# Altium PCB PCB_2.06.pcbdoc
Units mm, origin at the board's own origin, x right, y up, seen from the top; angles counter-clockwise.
Board outline 118.7 x 80.7 mm, 2 copper layers (Top Layer, Bottom Layer); 48 components, 30 nets, 171 pads, 58 vias.
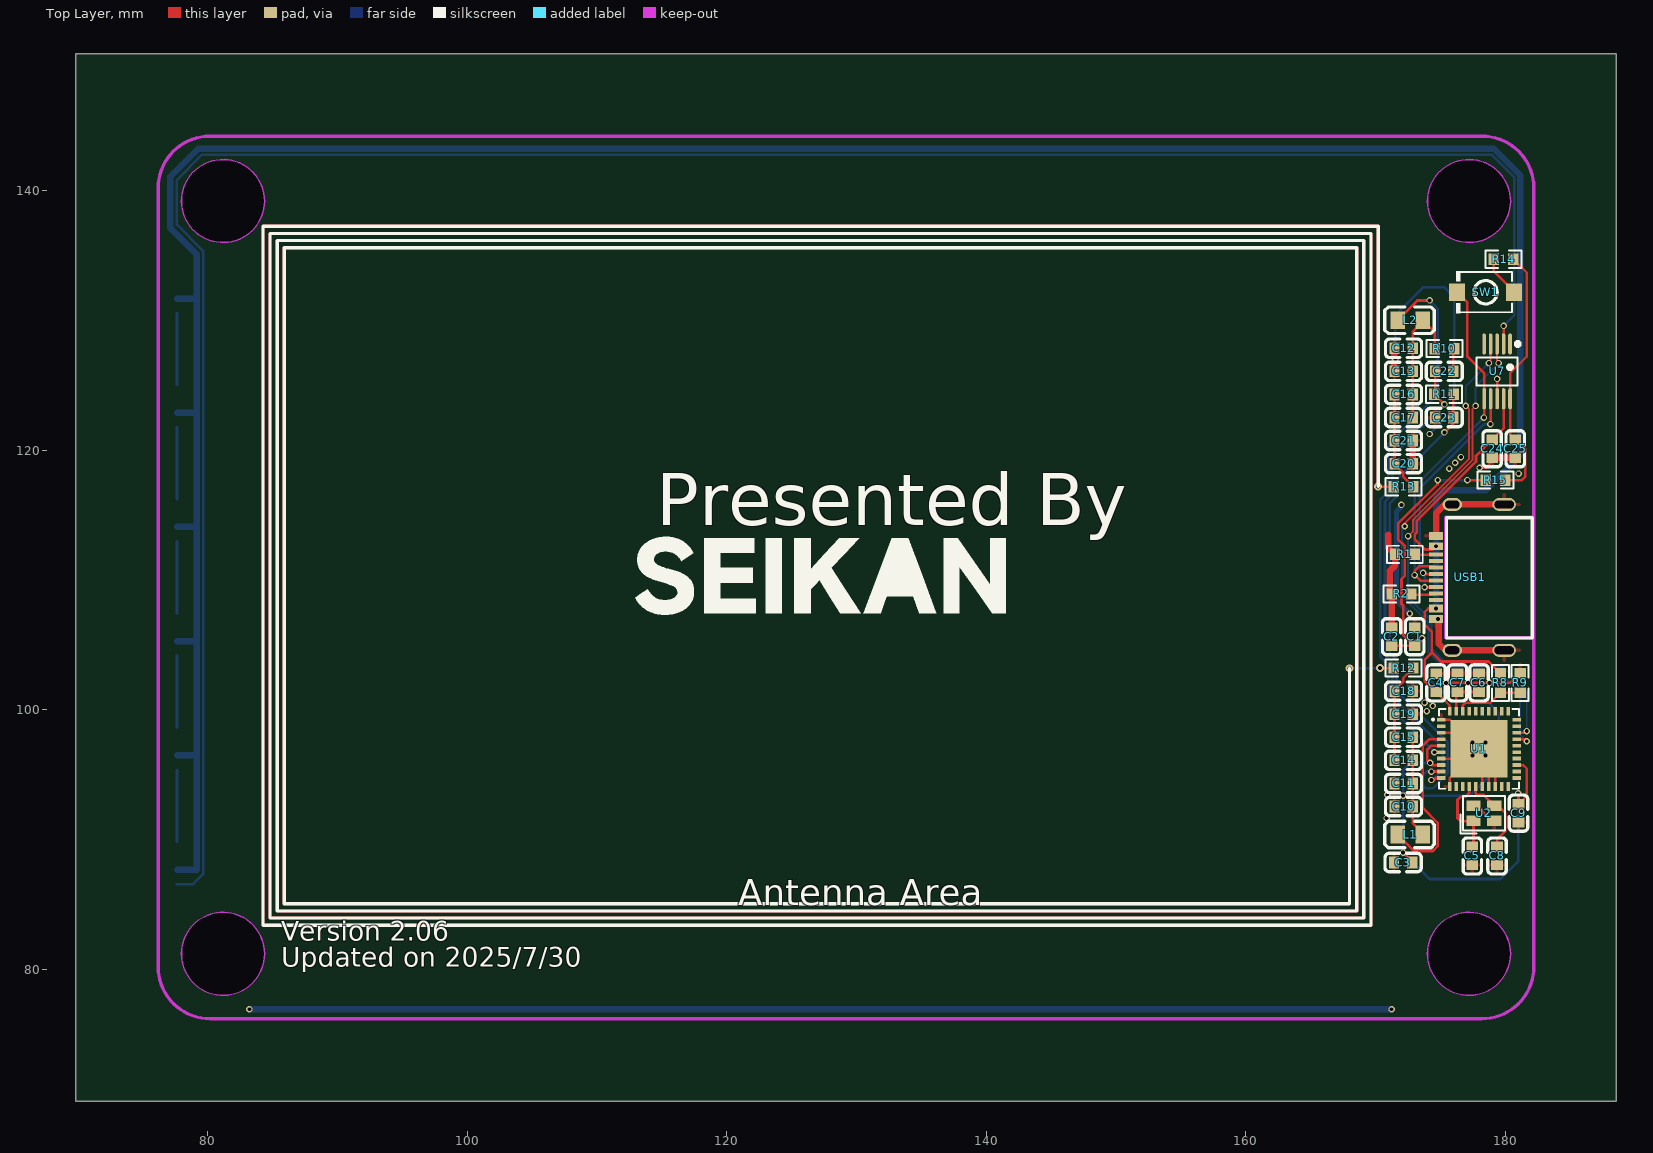
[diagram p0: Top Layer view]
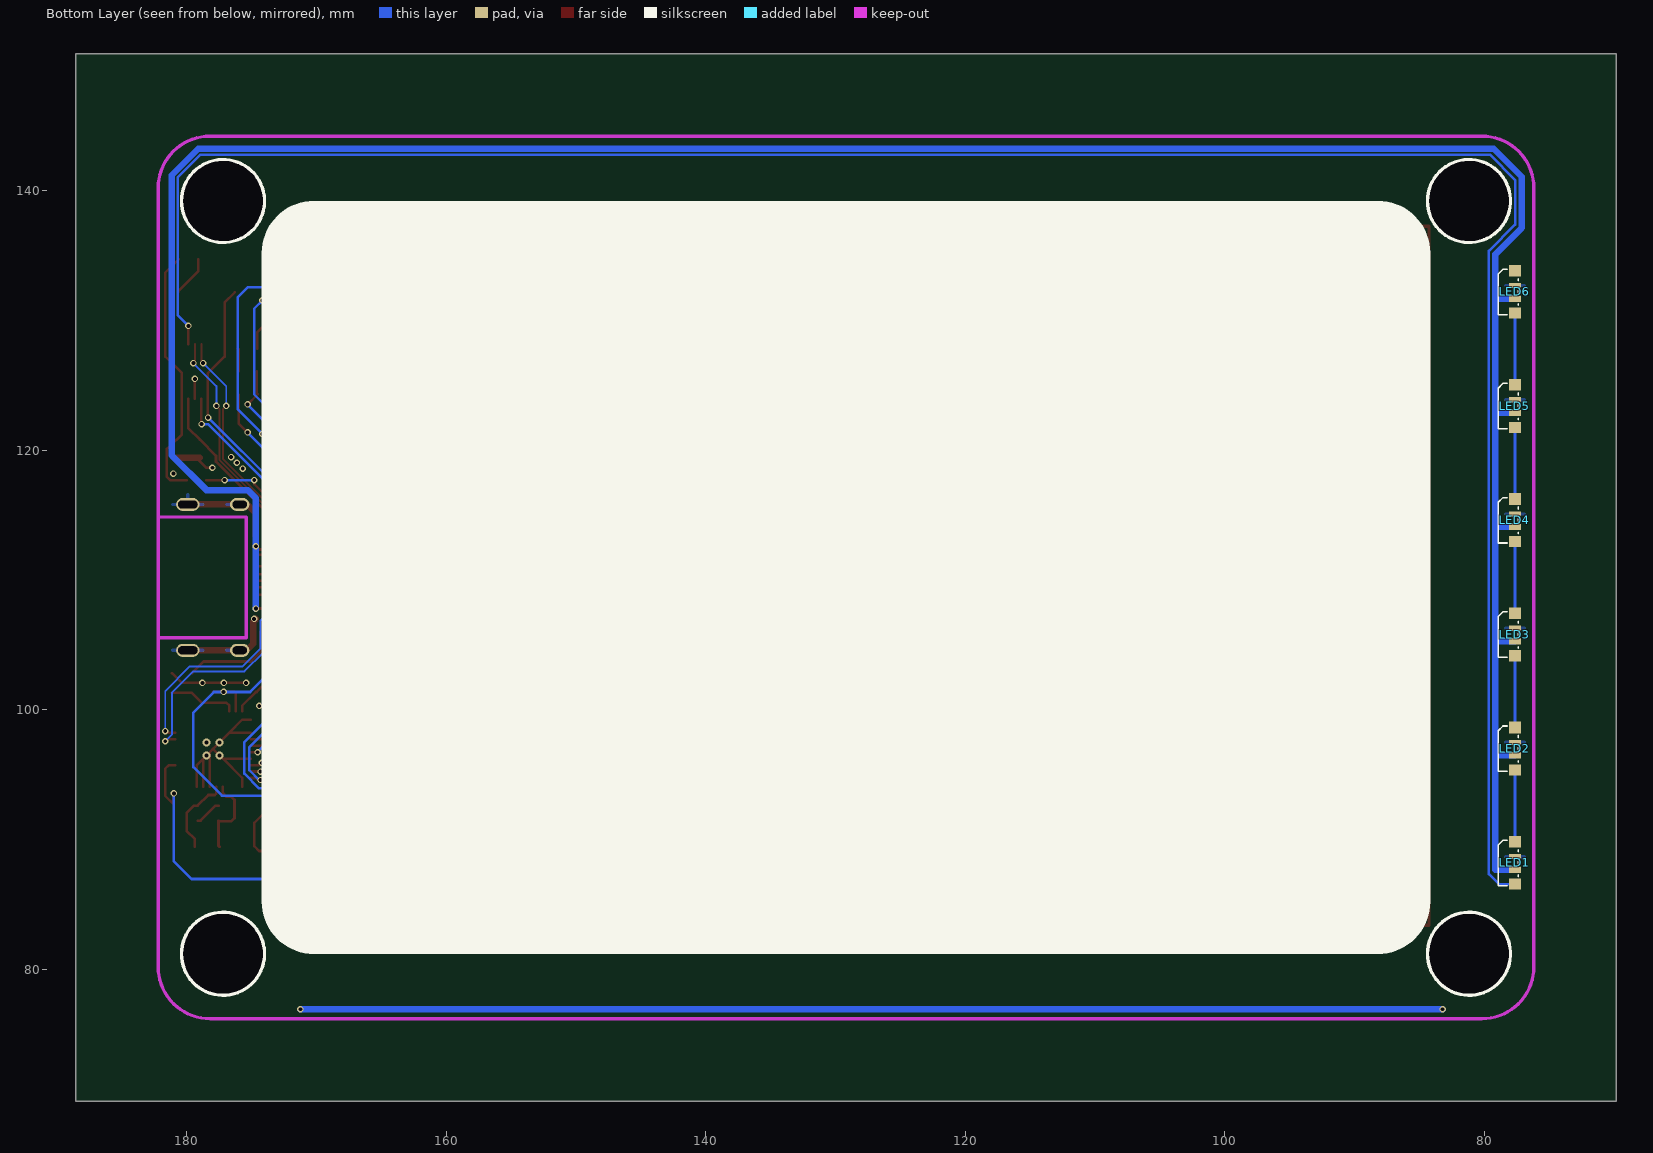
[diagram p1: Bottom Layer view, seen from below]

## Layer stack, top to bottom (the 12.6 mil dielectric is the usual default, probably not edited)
Top Layer: signal copper (thickness not stored)
Dielectric: dielectric 0.32, FR-4, Dk 4.8
Bottom Layer: signal copper (thickness not stored)

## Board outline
188.55,69.85 69.85,69.85 69.85,150.55 188.55,150.55
cut-out: 180.4,81.2 cw(c177.2,81.2) 174,81.2 cw(c177.2,81.2)
cut-out: 180.4,139.2 cw(c177.2,139.2) 174,139.2 cw(c177.2,139.2)
cut-out: 84.4,81.2 cw(c81.2,81.2) 78,81.2 cw(c81.2,81.2)
cut-out: 84.4,139.2 cw(c81.2,139.2) 78,139.2 cw(c81.2,139.2)

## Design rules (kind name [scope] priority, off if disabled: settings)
BoardOutlineClearance copperThickness1oz [All] p0: genericclearance=0.254 ignorepadtopadclearanceinfootprint=FALSE except(0: SMDPad-OutlineEdge Track-CutoutEdge SMDPad-CutoutEdge Arc-SplitContinuation Track-SplitContinuation SMDPad-SplitContinuation THPad-SplitContinuation Via-SplitContinuation Fill-SplitContinuation Poly-SplitContinuation Region-SplitContinuation Text-SplitContinuation; 0.152: THPad-CutoutEdge Via-CutoutEdge Fill-CutoutEdge Region-CutoutEdge; 0.3: Track-OutlineEdge THPad-OutlineEdge Via-OutlineEdge Fill-OutlineEdge Region-OutlineEdge Poly-OutlineEdge Text-OutlineEdge)
BoardOutlineClearance copperThickness2oz [All] p0: genericclearance=0.254 ignorepadtopadclearanceinfootprint=FALSE except(0: Arc-SplitContinuation Track-SplitContinuation SMDPad-SplitContinuation THPad-SplitContinuation Via-SplitContinuation Fill-SplitContinuation Poly-SplitContinuation Region-SplitContinuation Text-SplitContinuation; 0.152: SMDPad-CutoutEdge THPad-CutoutEdge Via-CutoutEdge Fill-CutoutEdge Region-CutoutEdge; 0.3: Track-OutlineEdge SMDPad-OutlineEdge THPad-OutlineEdge Via-OutlineEdge Fill-OutlineEdge Region-OutlineEdge Poly-OutlineEdge Text-OutlineEdge Track-CutoutEdge)
BoardOutlineClearance antenna [All] p0: genericclearance=0.254 ignorepadtopadclearanceinfootprint=FALSE except(0: Arc-SplitContinuation Track-SplitContinuation SMDPad-SplitContinuation THPad-SplitContinuation Via-SplitContinuation Fill-SplitContinuation Poly-SplitContinuation Region-SplitContinuation Text-SplitContinuation; 0.152: Track-CutoutEdge SMDPad-CutoutEdge THPad-CutoutEdge Via-CutoutEdge Fill-CutoutEdge Region-CutoutEdge; 0.3: Track-OutlineEdge SMDPad-OutlineEdge THPad-OutlineEdge Via-OutlineEdge Fill-OutlineEdge Region-OutlineEdge Poly-OutlineEdge Text-OutlineEdge)
Clearance copperThickness1oz [(InNet('TX1') OR InNet('TX2') OR InNet('GND') OR InNet('+3V3') OR InNet('VMID') OR InNet('RX') OR InNet('+5V') OR InNet('$1N4488') OR InNet('$1N4481') OR InNet('$1N4446') OR InNet('USB_DP') OR InNet('USB_DN') OR InNet('UART1_TX') OR InNet('UART1_RX') OR InNet('LED') OR InNet('$1N32752') OR InNet('$1N32754') OR InNet('ANTENNA') OR InNet('$1N926') OR InNet('$1N981') OR InNet('$1N39470') OR InNet('$1N39505') OR InNet('$1N2129') OR InNet('$1N39570') OR InNet('CH+3V3') OR InNet('$1N32106') OR InNet('$1N32105') OR InNet('$1N32099') OR InNet('$1N32096') OR InNet('$1N32092'))] p1: gap=0.178 ignorepadtopadclearanceinfootprint=FALSE except(0: Track-Region SMDPad-Region SMDPad-Sheet; 0.102: Track-Track; 0.152: Track-SMDPad SMDPad-SMDPad Track-THPad SMDPad-THPad THPad-THPad Track-Via SMDPad-Via THPad-Via Via-Via Track-Fill SMDPad-Fill THPad-Fill Via-Fill Fill-Fill THPad-Region Via-Region Fill-Region Region-Region Track-Poly SMDPad-Poly THPad-Poly Via-Poly Fill-Poly Poly-Poly Track-Text SMDPad-Text THPad-Text Via-Text Fill-Text Region-Text Poly-Text Text-Text Track-Hole SMDPad-Hole THPad-Hole Via-Hole Fill-Hole Region-Hole Poly-Hole Text-Hole; 0.3: Region-Poly Track-Sheet THPad-Sheet Via-Sheet Fill-Sheet Region-Sheet Poly-Sheet Text-Sheet Sheet-Hole)
Clearance copperThickness2oz [All] p1: gap=0.178 ignorepadtopadclearanceinfootprint=FALSE except(0.152: Track-SMDPad SMDPad-SMDPad Track-THPad SMDPad-THPad THPad-THPad Track-Via SMDPad-Via THPad-Via Via-Via Track-Fill SMDPad-Fill THPad-Fill Via-Fill Fill-Fill SMDPad-Region THPad-Region Via-Region Fill-Region Region-Region Track-Poly SMDPad-Poly THPad-Poly Via-Poly Fill-Poly Poly-Poly Track-Text SMDPad-Text THPad-Text Via-Text Fill-Text Region-Text Poly-Text Text-Text Track-Hole SMDPad-Hole THPad-Hole Via-Hole Fill-Hole Region-Hole Poly-Hole Text-Hole; 0.203: Track-Track; 0.3: Track-Region Region-Poly Track-Sheet SMDPad-Sheet THPad-Sheet Via-Sheet Fill-Sheet Region-Sheet Poly-Sheet Text-Sheet Sheet-Hole)
Clearance antenna [All] p1: gap=0.178 ignorepadtopadclearanceinfootprint=FALSE except(0.152: Track-SMDPad SMDPad-SMDPad Track-THPad SMDPad-THPad THPad-THPad Track-Via SMDPad-Via THPad-Via Via-Via Track-Fill SMDPad-Fill THPad-Fill Via-Fill Fill-Fill Track-Region SMDPad-Region THPad-Region Via-Region Fill-Region Region-Region Track-Poly SMDPad-Poly THPad-Poly Via-Poly Fill-Poly Region-Poly Poly-Poly Track-Text SMDPad-Text THPad-Text Via-Text Fill-Text Region-Text Poly-Text Text-Text Track-Hole SMDPad-Hole THPad-Hole Via-Hole Fill-Hole Region-Hole Poly-Hole Text-Hole; 0.3: Track-Track Track-Sheet SMDPad-Sheet THPad-Sheet Via-Sheet Fill-Sheet Region-Sheet Poly-Sheet Text-Sheet Sheet-Hole)
DiffPairsRouting differentialPair [All] p1: maxuncoupledlength=10 minlimit=5.9843 maxlimit=5.9843 mostfreqgap=5.9843 toplayer_minwidth=5 toplayer_prefwidth=10 toplayer_maxwidth=100 bottomlayer_minwidth=5 bottomlayer_prefwidth=10 bottomlayer_maxwidth=100
PasteMaskExpansion pasteMaskExpansion [All] p1: expansion=0
PlaneConnect innerPlane [All] p1: planeconnectstyle=Relief reliefexpansion=0.508 reliefentries=4 reliefconductorwidth=0.254 reliefairgap=0.254
PolygonConnect copperRegion [All] p1: connectstyle=Relief reliefentries=4 reliefconductorwidth=10 polygonreliefangle="90 Angle" airgapwidth=10
RoutingVias viaSize [All] p1: viastyle="Through Hole" holewidth=12.0078 minholewidth=11.811 maxholewidth=248.0314 width=24.0158 minwidth=19.685 maxwidth=393.7008
SolderMaskExpansion solderMaskExpansion [All] p1: useseparateexpansions=TRUE expansion=2.0079 expansionbottom=2.0079
Width copperThickness1oz [All] p1: maxlimit=100 minlimit=5 preferedwidth=10
Width copperThickness2oz [All] p1: maxlimit=100 minlimit=8 preferedwidth=10
Width antenna [All] p1: maxlimit=10 minlimit=10 preferedwidth=10

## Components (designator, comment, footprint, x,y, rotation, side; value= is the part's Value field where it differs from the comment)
C1 "CAP_0603" C0603 173.021,105.632 r270 top
C2 "CAP_0603" C0603 171.243,105.632 r270 top
C3 "CAP_0603" C0603 172.126,88.229 r0 top
C4 "CAP_0603" C0603 174.666,102.072 r270 top
C5 "CAP_0603" C0603 177.46,88.737 r90 top
C6 "CAP_0603" C0603 177.968,102.072 r270 top
C7 "CAP_0603" C0603 176.317,102.072 r270 top
C8 "CAP_0603" C0603 179.365,88.737 r90 top
C9 "CAP_0603" C0603 181.016,92.039 r90 top
C10 "CAP_0603" C0603 172.158,92.547 r0 top
C11 "CAP_0603" C0603 172.158,94.325 r0 top
C12 "CAP_0603" C0603 172.158,127.853 r0 top
C13 "CAP_0603" C0603 172.158,126.075 r180 top
C14 "CAP_0603" C0603 172.158,96.103 r0 top
C15 "CAP_0603" C0603 172.158,97.881 r0 top
C16 "CAP_0603" C0603 172.158,124.297 r0 top
C17 "CAP_0603" C0603 172.158,122.519 r0 top
C18 "CAP_0603" C0603 172.158,101.437 r180 top
C19 "CAP_0603" C0603 172.158,99.659 r180 top
C20 "CAP_0603" C0603 172.158,118.963 r180 top
C21 "CAP_0603" C0603 172.158,120.741 r0 top
C22 "CAP_0603" C0603 175.301,126.075 r0 top
C23 "CAP_0603" C0603 175.301,122.519 r180 top
C24 "CAP_0603" C0603 178.985,120.111 r270 top
C25 "CAP_0603" C0603 180.767,120.105 r270 top
L1 "SDFL2012LR56KTF" L0805 172.666,90.388 r0 top
L2 "SDFL2012LR56KTF" L0805 172.666,130.012 r0 top
LED1 "3512侧面幻彩SK6812B-3512" LED-SMD_SK6812B-3512 77.656,88.2 r270 bottom
LED2 "3512侧面幻彩SK6812B-3512" LED-SMD_SK6812B-3512 77.656,97 r270 bottom
LED3 "3512侧面幻彩SK6812B-3512" LED-SMD_SK6812B-3512 77.656,105.8 r270 bottom
LED4 "3512侧面幻彩SK6812B-3512" LED-SMD_SK6812B-3512 77.656,114.6 r270 bottom
LED5 "3512侧面幻彩SK6812B-3512" LED-SMD_SK6812B-3512 77.656,123.4 r270 bottom
LED6 "3512侧面幻彩SK6812B-3512" LED-SMD_SK6812B-3512 77.656,132.2 r270 bottom
R1 "Res_0603" R0603 172.253,111.978 r180 top
R2 "Res_0603" R0603 171.999,108.93 r0 top
R8 "Res_0603" R0603 179.619,102.072 r270 top
R9 "Res_0603" R0603 181.143,102.072 r90 top
R10 "Res_0603" R0603 175.306,127.825 r0 top
R11 "Res_0603" R0603 175.277,124.311 r0 top
R12 "Res_0603" R0603 172.158,103.215 r180 top
R13 "Res_0603" R0603 172.158,117.185 r180 top
R14 "Res_0603" R0603 179.873,134.711 r180 top
R15 "Res_0603" R0603 179.238,117.693 r180 top
SW1 "TS-1088-AR02016" SW-SMD_L3.9-W3.0-P4.45 178.476,132.171 r180 top
U1 "PN5321A3HN/C106,55" QFN-40_L6.0-W6.0-P0.50-BL-EP 177.968,96.992 r270 top
U2 "ECS-271.2-10-37-CKM-TR" CRYSTAL-SMD_4P-L2.0-W1.6-BL-2 178.349,92.039 r0 top
U7 "CH552E" MSOP-10_L3.0-W3.0-P0.50-LS5.0-BL 179.365,126.075 r180 top
USB1 "HX TYPE-C 16P CB0.8" USB-C-SMD_HX-TYPE-C-16P-CB0.8 177.289,110.2 r90 top

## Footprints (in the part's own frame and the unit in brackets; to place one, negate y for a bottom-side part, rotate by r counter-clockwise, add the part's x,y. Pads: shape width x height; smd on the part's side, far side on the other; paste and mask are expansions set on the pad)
C0603 [mm]
  rect 0.8x0.9 smd: 1(-0.7,0) 2(0.7,0)
  silkscreen extent -1.39,-0.71 1.39,0.71
CRYSTAL-SMD_4P-L2.0-W1.6-BL-2 [mm]
  rect 1.1x0.8 smd: 1(-0.8,-0.575) 2(0.8,-0.575) 3(0.8,0.575) 4(-0.8,0.575)
  silkscreen extent -1.82,-1.56 1.64,1.33
L0805 [mm]
  rect 1.133x1.377 smd: 1(-0.966,0) 2(0.966,0)
  silkscreen extent -1.95,-1.02 1.86,1.02
LED-SMD_SK6812B-3512 [mm]
  rect 0.9x0.9 smd: 1(-1.638,0)
  rect 0.4x0.9 smd: 2(-0.487,0)
  rect 0.5x0.9 smd: 3(0.513,0)
  rect 0.85x0.9 smd: 4(1.638,0)
  silkscreen extent -1.75,-1.3 1.75,0.25
MSOP-10_L3.0-W3.0-P0.50-LS5.0-BL [mm]
  oval 0.28x1.62 smd: 1(-1,-2.11) 2(-0.5,-2.11) 3(0,-2.11) 4(0.5,-2.11) 5(1,-2.11) 6(1,2.11) 7(0.5,2.11) 8(0,2.11) 9(-0.5,2.11) 10(-1,2.11)
  silkscreen extent -1.74,-2.26 1.58,1.07
QFN-40_L6.0-W6.0-P0.50-BL-EP [mm]
  rect 0.28x0.665 smd: 1(-2.25,-2.908) 2(-1.75,-2.908) 3(-1.25,-2.908) 4(-0.75,-2.908) 5(-0.25,-2.908) 6(0.25,-2.908) 7(0.75,-2.908) 8(1.25,-2.908) 9(1.75,-2.908) 10(2.25,-2.908) 21(2.25,2.908) 22(1.75,2.908) 23(1.25,2.908) 24(0.75,2.908) 25(0.25,2.908) 26(-0.25,2.908) 27(-0.75,2.908) 28(-1.25,2.908) 29(-1.75,2.908) 30(-2.25,2.908)
  rect 0.665x0.28 smd: 11(2.908,-2.25) 12(2.908,-1.75) 13(2.908,-1.25) 14(2.908,-0.75) 15(2.908,-0.25) 16(2.908,0.25) 17(2.908,0.75) 18(2.908,1.25) 19(2.908,1.75) 20(2.908,2.25) 31(-2.908,2.25) 32(-2.908,1.75) 33(-2.908,1.25) 34(-2.908,0.75) 35(-2.908,0.25) 36(-2.908,-0.25) 37(-2.908,-0.75) 38(-2.908,-1.25) 39(-2.908,-1.75) 40(-2.908,-2.25)
  rect 4.42x4.42 smd: 41(0,0)
  silkscreen extent -3.08,-3.61 3.08,3.08
R0603 [mm]
  rect 0.806x0.864 smd: 1(-0.753,0) 2(0.753,0)
  silkscreen extent -1.39,-0.66 1.39,0.66
SW-SMD_L3.9-W3.0-P4.45 [mm]
  rect 1.23x1.36 smd: 1(-2.185,0) 2(2.185,0)
  silkscreen extent -2.03,-1.62 2.25,1.62
USB-C-SMD_HX-TYPE-C-16P-CB0.8 [mm]
  oval 1x1.5 hole 0.6 slot 1.1 at 90 deg: 25(5.62,1.375) 28(-5.62,1.375)
  oval 1x1.8 hole 0.6 slot 1.5 at 90 deg copper offset 0,0: 26(5.62,-2.625) 27(-5.62,-2.625)
  rect 0.6x1.1 smd: A1B12(-3.2,2.625) A4B9(-2.4,2.625) B1A12(3.2,2.625) B4A9(2.4,2.625)
  rect 0.3x1.1 smd: A5(-1.25,2.625) A6(-0.25,2.625) A7(0.25,2.625) A8(1.25,2.625) B5(1.75,2.625) B6(0.75,2.625) B7(-0.75,2.625) B8(-1.75,2.625)
  Board Outline Layer lines w0.254: -4.65,1.874 -4.65,-4.725 -4.65,1.874 ; -4.65,1.874 4.65,1.874 ; -4.65,1.874 4.65,1.874 ; 4.65,1.874 4.65,-4.725 4.65,1.874
  silkscreen extent -4.67,-4.78 4.6,1.82

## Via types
v1: diameter 0.5, hole 0.3, Top Layer to Bottom Layer, 51 vias
v2: diameter 0.61, hole 0.305, Top Layer to Bottom Layer, 7 vias

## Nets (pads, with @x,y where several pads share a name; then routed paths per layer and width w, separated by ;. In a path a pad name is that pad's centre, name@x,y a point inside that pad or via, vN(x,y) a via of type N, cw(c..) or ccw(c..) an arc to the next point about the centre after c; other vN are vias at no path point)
$1N926: C10.2 C11.2 C14.2 C15.2 L1.2 | length 7.8
  Top Layer w0.2: C15.2 C14.2 C11.2 C10.2 172.858,91.284 173.632,90.51 L1.2
$1N981: C12.2 C13.1 C16.2 C17.2 L2.2 R10.1 | length 10.4
  Top Layer w0.2: C17.2 C16.2 C13.1 C12.2 172.858,129.116 173.632,129.89 L2.2 174.552,129.092 R10.1
$1N2129: C22.2 R10.2 | length 1.8
  Top Layer w0.2: C22.2 176.001,127.767 R10.2
$1N4446: R8.2 R9.1 U1.38 | length 5.3
  Top Layer w0.2: U1.38 176.718,100.314 176.952,100.548 178.848,100.548 R8.2 R9.1
$1N4481: C8.2 U1.15 U2.3 | length 6.3
  Top Layer w0.2: U1.15 177.718,93.559 177.841,93.436 178.327,93.436 U2.3 179.425,92.614 180,92.039 180,90.672 179.365,90.037 C8.2
$1N4488: C5.2 U1.14 U2.1 | length 6.4
  Top Layer w0.2: U1.14 177.218,93.575 176.952,93.309 176.571,93.309 176.317,93.055 176.317,91.658 176.571,91.404 177.489,91.404 U2.1 177.549,89.526 C5.2
$1N32092: LED5.1 LED6.4 | length 5.5
  Bottom Layer w0.2: LED5.1 LED6.4
$1N32096: LED4.1 LED5.4 | length 5.5
  Bottom Layer w0.2: LED4.1 LED5.4
$1N32099: LED3.1 LED4.4 | length 5.5
  Bottom Layer w0.2: LED3.1 LED4.4
$1N32105: LED2.1 LED3.4 | length 5.5
  Bottom Layer w0.2: LED2.1 LED3.4
$1N32106: LED1.1 LED2.4 | length 5.5
  Bottom Layer w0.2: LED1.1 LED2.4
$1N32752: R1.1 USB1.B5 | length 1.7
  Top Layer w0.2: R1.1 173.034,111.95 USB1.B5
$1N32754: R2.2 USB1.A5 | length 1.7
  Top Layer w0.2: R2.2@173.006,108.93 173.084,108.852 174.566,108.852 USB1.A5
$1N39470: C14.1 C15.1 C18.2 C19.2 R12.1 | length 7.7
  Top Layer w0.2: C14.1 C15.1 C19.2 C18.2 171.458,101.487 172.126,102.155 172.126,102.43 R12.1
$1N39505: C16.1 C17.1 C20.2 C21.1 R13.1 | length 7.7
  Top Layer w0.2: C16.1 C17.1 C21.1 C20.2 172.126,118.295 172.126,117.97 R13.1
$1N39570: R14.2 SW1.1 | length 3.2
  Top Layer w0.2: R14.2 179.12,133.777 180.661,132.236 SW1.1
+3V3: C1.2 C2.2 C3.2 C6.2 C7.2 C9.2 R15.2 U1.5 U1.8 U1.23 U1.39 | length 79.6
  Top Layer w0.2: C2.2 C1.2@172.971,104.932 ; v1(172.126,88.991) 172.826,88.291 C3.2 ; v1(173.588,105.505) 173.021,104.938 C1.2 C1.2@172.971,104.932 ; v1(174.793,117.693) 174.793,117.387 171.745,114.339 171.745,113.121 172.253,112.613 172.253,110.327 171.999,110.073 171.999,108.168 172.126,108.041 172.126,105.777 C1.2@172.971,104.932 ; U1.8 174.369,95.742 v1(174.21,95.901) 173.988,96.123 173.988,96.949 174.281,97.242 U1.5 ; U1.39 176.218,101.273 C7.2 v1(177.154,101.372) C6.2 ; v1(177.079,117.693) R15.2 ; U1.23 181.377,95.742 181.651,95.468 181.651,93.374 C9.2 181.016,93.529 v1(180.982,93.563)
  Bottom Layer w0.2: v1(173.588,105.505) 173.588,102.896 175.112,101.372 v1(177.154,101.372) 177.906,101.372 179.492,99.786 179.492,95.595 177.284,93.387 v1(172.126,93.387) ; v1(174.21,95.901) 172.686,95.901 172.126,95.341 v1(172.126,93.387) ; v1(174.793,117.693) v1(177.079,117.693) ; v1(180.982,93.563) 180.982,88.322 179.619,86.959 174.158,86.959 v1(172.126,88.991) v1(172.126,93.387)
+5V: C4.2 C24.1 LED1.3 LED2.3 LED3.3 LED4.3 LED5.3 LED6.3 R8.1 U1.40 U7.9 USB1.A4B9 USB1.B4A9 | length 238.5
  Top Layer w0.2: v1(174.664,107.8) 174.062,107.8 173.777,107.515 173.777,106.562 174.344,105.995 174.344,104.417 ; v1(174.664,112.6) 174.416,112.352 173.824,112.352 173.009,113.167 173.009,113.485 173.165,113.641 173.165,114.543 177.737,119.115 177.737,119.563 C24.1 179.865,121.691 U7.9 ; U1.40 175.718,100.32 C4.2 174.616,101.372 173.777,102.211 173.777,103.85 174.344,104.417 ; R8.1 179.59,102.825 178.693,103.723 175.039,103.723 174.344,104.417
  Bottom Layer w0.2: v1(174.664,107.8) v1@174.666,107.798
  Bottom Layer w0.5: LED1.3 79.162,87.687 79.162,96.487 ; LED2.3 79.162,96.487 ; LED3.3 79.162,105.287 ; LED4.3 79.162,114.087 ; LED5.3 79.162,122.887 ; LED6.3 79.162,131.687 ; v1(174.664,107.8) v1(174.664,112.6) 174.664,116.294 175.301,116.931 178.476,116.931 181.143,119.598 181.143,141.188 179.111,143.22 79.289,143.22 77.13,141.061 77.13,137.124 79.162,135.092 79.162,131.687 ; 79.162,96.487 79.162,105.287 ; 79.162,105.287 79.162,114.087 ; 79.162,114.087 79.162,122.887 ; 79.162,122.887 79.162,131.687
ANTENNA: R12.2 R13.2 | length 1080.2
  Top Layer w0.2: v2(170.2,117.2) 171.39,117.2 R13.2 ; v2(170.348,103.215) R12.2
  Top Layer w0.25: v2(168,103.2) 168,85.053 85.924,85.053 85.924,135.601 168.55,135.601 168.55,84.503 85.374,84.503 85.374,136.151 169.1,136.151 169.1,83.953 84.824,83.953 84.824,136.701 169.65,136.701 169.65,83.403 84.274,83.403 84.274,137.251 170.2,137.251 v2(170.2,117.2)
  Bottom Layer w0.2: v2(168,103.2) 168.015,103.215 v2(170.348,103.215)
CH+3V3: C25.1 R14.1 R15.1 U7.10 | length 19.9
  Top Layer w0.2: R15.1 181.27,117.693 181.524,117.947 181.524,120.098 180.817,120.805 C25.1 180.365,121.207 U7.10 180.365,125.932 181.651,127.218 181.651,133.686 R14.1
GND: C1.1 C2.1 C3.1 C4.1 C5.1 C6.1 C7.1 C8.1 C9.1 C10.1 C11.1 C12.1 C13.2 C18.1 C19.1 C20.1 C21.2 C23.2 C24.2 C25.2 LED1.2 LED2.2 LED3.2 LED4.2 LED5.2 LED6.2 R1.2 R2.1 R9.2 U1.1 U1.3 U1.7 U1.11 U1.16 U1.17 U1.18 U1.41 U2.2 U2.4 U7.8 USB1.25 USB1.26 USB1.27 USB1.28 USB1.A1B12 USB1.B1A12 | length 175.8
  Top Layer w0.2: U1.7 U1.41@177.218,96.242 ; U1.3 U1.41@176.718,98.242 ; U1.1 175.718,99.242 U1.41@176.718,98.242 ; v1(175.428,102.072) v1(177.131,102.072) v1(178.794,102.072) 180.361,102.072 181.114,102.825 R9.2 ; U1.11 175.718,94.742 U1.41@177.218,96.242 ; U2.4 177.774,92.614 178.924,91.464 U2.2 ; v1(178.016,118.645) 178.473,118.645 C24.2@179.239,119.411 ; U1.16 U1.41@178.218,96.742 ; U1.17 U1.41@178.718,96.242 ; U1.18 179.218,95.742 U1.41@178.718,96.242 ; U7.8 v1(179.365,125.496) ; U1.41@176.718,98.242 v2(177.468,97.492) U1.41 ; U1.41@177.218,96.242 v2(177.468,96.492) U1.41 ; U1.41 U1.41@178.218,96.742 ; U1.41@178.218,96.742 v2(178.468,96.492) U1.41@178.718,96.242
  Top Layer w0.5: 170.983,113.502 170.983,112.495 R1.2 171.5,111.098 171.11,110.708 171.11,109.066 R2.1 171.246,106.335 C2.1 ; C13.2 C12.1 ; C20.1 C21.2 ; USB1.A1B12 174.865,106.799 174.865,105.08 175.365,104.58 USB1.28 USB1.27 ; USB1.B1A12 174.664,115.151 175.333,115.82 USB1.25 USB1.26 ; C24.2 179.239,119.411 180.761,119.411 C25.2
  Bottom Layer w0.2: v1(171.523,127.004) 171.523,130.425 173.65,132.552 175.301,132.552 176.063,131.79 176.063,123.154 v1(174.158,121.249)
  Bottom Layer w0.4: v1(171.999,115.788) 171.999,115.661 171.618,115.28 171.618,108.422 v1(172.634,107.406)
  Bottom Layer w0.5: v1(83.226,76.926) v1(171.237,76.926)
  other v1: 170.856,91.658 170.899,93.436 173.946,99.893 174.412,100.294 173.777,100.548 174.8,107 181.016,118.201 175.682,118.582 176.135,119.031 176.571,119.471
  other v2: 178.468,97.492
LED: LED1.4 U7.2 | length 174.4
  Top Layer w0.2: U7.2 v1(179.865,129.582)
  Bottom Layer w0.2: LED1.4 78.892,86.562 79.67,87.34 79.67,135.346 77.638,137.378 77.638,140.807 79.599,142.768 178.924,142.768 180.691,141.001 180.691,130.408 v1(179.865,129.582)
RX: C22.1 R11.1 U1.10 | length 36.8
  Top Layer w0.2: v1(174.298,94.59) 174.514,94.59 174.666,94.742 U1.10 ; C22.1 174.601,124.388 R11.1 v1(175.301,123.535)
  Bottom Layer w0.2: v1(174.298,94.59) 174.423,94.59 175.174,95.341 175.174,97.119 171.285,101.008 171.285,103.675 170.729,104.231 170.729,116.042 171.285,116.598 171.285,119.519 v1(175.301,123.535)
TX1: L1.1 U1.4 | length 13.6
  Top Layer w0.2: L1.1 172.97,89.118 174.412,89.118 174.793,89.499 174.793,91.277 173.65,92.42 173.65,97.246 174.146,97.742 U1.4
TX2: L2.1 U1.6 | length 42.4
  Top Layer w0.2: L2.1 173.224,131.536 v1(174.158,131.536) ; v1(174.53,96.732) 175.177,96.732 U1.6@175.187,96.742
  Bottom Layer w0.2: v1(174.158,131.536) 174.793,130.901 174.793,124.297 170.983,120.487 170.983,116.804 170.36,116.181 170.36,104.092 170.983,103.469 170.983,100.278 v1(174.53,96.732)
UART1_RX: U1.27 U7.4 | length 40.8
  Top Layer w0.15: v1(172.253,114.137) 172.253,114.38 177.206,119.333 177.206,123.154 v1(176.952,123.408) ; v1(178.73,126.71) 178.865,126.845 U7.4
  Top Layer w0.2: U1.27 181.487,97.742 v1(181.65,97.579)
  Bottom Layer w0.15: v1(172.253,114.137) 172.022,113.906 172.022,108.78 174.065,106.737 174.065,104.451 175.555,102.961 179.492,102.961 181.143,101.31 181.143,98.086 v1(181.65,97.579) ; v1(176.952,123.408) 176.952,124.932 v1(178.73,126.71)
UART1_TX: U1.28 U7.3 | length 39.8
  Top Layer w0.15: v1(172.507,113.375) 172.888,113.756 172.888,114.658 177.46,119.23 177.46,123.154 v1(177.714,123.408) ; U7.3 179.365,126.83 v1(179.485,126.71)
  Top Layer w0.2: U1.28 181.529,98.242 v1(181.65,98.363)
  Bottom Layer w0.15: v1(172.507,113.375) 172.507,108.651 174.317,106.841 174.317,104.707 175.682,103.342 179.746,103.342 181.65,101.438 v1(181.65,98.363) ; v1(177.714,123.408) 177.714,124.939 v1(179.485,126.71)
USB_DN: U7.7 USB1.A7 USB1.B7 | length 19.2
  Top Layer w0.2: v1(173.66,110.54) 173.75,110.45 USB1.A7 ; v1(173.777,109.438) 173.789,109.45 USB1.B7 ; v1(178.857,122.011) 178.865,122.019 U7.7
  Bottom Layer w0.2: v1(173.777,109.438) 173.777,110.423 v1(173.66,110.54) 173.396,110.804 173.396,117.058 178.349,122.011 v1(178.857,122.011)
USB_DP: SW1.2 U7.6 USB1.A6 USB1.B6 | length 28.8
  Top Layer w0.2: USB1.A6 173.446,109.95 v1(173.015,110.381) 173.015,110.708 173.355,111.048 174.566,111.048 USB1.B6 ; SW1.2 177.079,131.383 177.079,127.218 178.365,125.932 U7.6 178.365,122.535 v1(178.349,122.519)
  Bottom Layer w0.2: v1(173.015,110.381) 173.015,117.185 v1(178.349,122.519)
VMID: C23.1 R11.2 U1.9 | length 38
  Top Layer w0.2: v1(174.298,95.242) U1.9 ; v1(175.301,121.376) 176.001,122.076 C23.1 176.001,124.282 R11.2
  Bottom Layer w0.2: v1(174.298,95.242) 173.932,95.242 173.523,94.833 173.523,94.325 173.904,93.944 174.412,93.944 175.555,95.087 175.555,97.5 171.618,101.437 171.618,103.85 171.11,104.358 171.11,115.915 171.587,116.392 171.587,117.662 v1(175.301,121.376)
pads on no net: LED6.1 U1.2 U1.12 U1.13 U1.19 U1.20 U1.21 U1.22 U1.24 U1.25 U1.26 U1.29 U1.30 U1.31 U1.32 U1.33 U1.34 U1.35 U1.36 U1.37 U7.1 U7.5 USB1.A8 USB1.B8

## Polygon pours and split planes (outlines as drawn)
GND on Bottom Layer (solid, remove dead copper, pour order 2): 170.7,144.2 182.2,144.2 182.2,76.2 170.7,76.2
GND on Top Layer (solid, remove dead copper, pour order 0): 170.7,144.2 182.2,144.2 182.2,76.2 170.7,76.2
GND on Bottom Layer (solid, remove dead copper, pour order 4): 76.2,144.2 83.7,144.2 83.7,76.2 76.2,76.2

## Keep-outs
Board Outline Layer:
  circle w0.025: c177.2,81.2 r3.2
  region: 180.4,81.2 cw(c177.2,81.2) 174,81.2 cw(c177.2,81.2)
  circle w0.025: c177.2,139.2 r3.2
  region: 180.4,139.2 cw(c177.2,139.2) 174,139.2 cw(c177.2,139.2)
  circle w0.025: c81.2,81.2 r3.2
  region: 84.4,81.2 cw(c81.2,81.2) 78,81.2 cw(c81.2,81.2)
  circle w0.025: c81.2,139.2 r3.2
  region: 84.4,139.2 cw(c81.2,139.2) 78,139.2 cw(c81.2,139.2)
  lines w0.254: 76.2,80.2 ccw(c80.2,80.2) 80.2,76.2 178.2,76.2 ccw(c178.2,80.2) 182.2,80.2 182.2,140.2 ccw(c178.2,140.2) 178.2,144.2 80.2,144.2 ccw(c80.2,140.2) 76.2,140.2 76.2,80.2

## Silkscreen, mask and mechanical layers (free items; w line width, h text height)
Top Silkscreen Layer:
  drawing of 23 lines, arcs and shapes, not listed
  text "Presented By" at 114.582,114.2 h4
  text "Antenna Area" at 120.89,84.927 h2
  text "Version 2.06" at 85.7,82.2 h1.5
  text "Updated on 2025/7/30" at 85.7,80.2 h1.5
Bottom Silkscreen Layer:
  circle w0.254: c177.2,81.2 r3.2
  circle w0.254: c177.2,139.2 r3.2
  circle w0.254: c81.2,139.2 r3.2
  circle w0.254: c81.2,81.2 r3.2
  region: 88.2,139.2 170.2,139.2 cw(c170.2,135.2) 174.2,135.2 174.2,85.2 cw(c170.2,85.2) 170.2,81.2 88.2,81.2 cw(c88.2,85.2) 84.2,85.2 84.2,135.2 cw(c88.2,135.2)
Top Solder Mask Layer:
  lines w0.2: 168,85.053 168,103.2
Mechanical Layer:
  circle w0.025: c177.2,81.2 r3.2
  circle w0.025: c177.2,139.2 r3.2
  circle w0.025: c81.2,81.2 r3.2
  circle w0.025: c81.2,139.2 r3.2
Mech6:
  lines w0.254: 84.2,83.2 170.2,83.2 170.2,137.2 84.2,137.2 84.2,83.2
